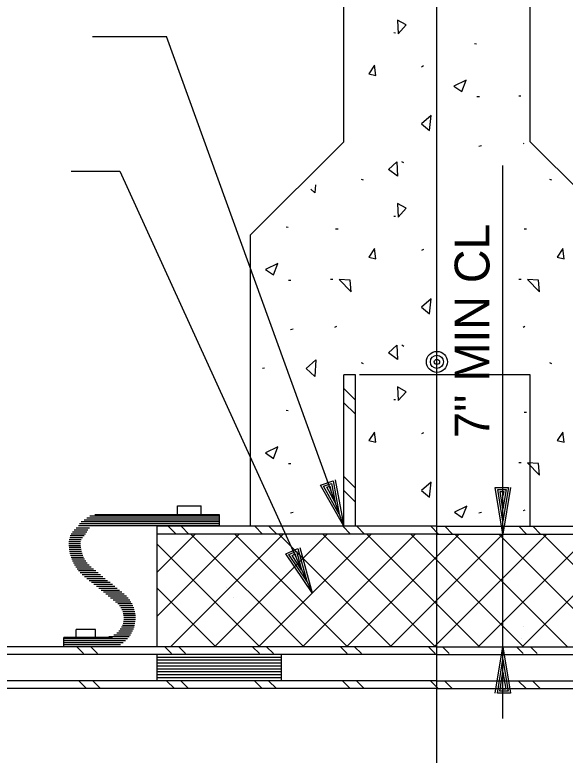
# Model space of a CAD drawing. Extents: x 22422.9 to 22498.9, y 22369.6 to 22415.
# Drawn here: x 22428.867 to 22431.818, y 22392.447 to 22396.418 of the extents above; entities that cross this region are included whole.
import ezdxf

# ---------------------------------------------------------------- set-up
doc = ezdxf.new("R2010")
doc.units = 0
for name, color, linetype in [('Level 1', 7, 'Continuous'), ('Level 2', 7, 'Continuous'), ('Level 4', 7, 'Continuous'), ('Level 44', 7, 'Continuous'), ('Level 7', 7, 'Continuous'), ('Level 8', 7, 'Continuous')]:
    doc.layers.add(name, color=color, linetype=linetype)

msp = doc.modelspace()

# ---------------------------------------------------------------- linework, layer by layer
at = {"layer": 'Level 1'}
for p, q in [((22431.1304, 22388.8739), (22431.1304, 22398.3655)), ((22431.4842, 22393.6331), (22431.4842, 22395.6099)), ((22430.6068, 22393.865), (22430.6068, 22393.865)), ((22430.6304, 22393.7998), (22430.6304, 22393.7998)), ((22429.7392, 22393.7364), (22429.7392, 22393.7841)), ((22429.7392, 22393.7841), (22429.8666, 22393.7841)), ((22429.8666, 22393.7364), (22429.8666, 22393.7841)), ((22429.6304, 22393.029), (22429.6304, 22393.6748)), ((22431.1304, 22393.6748), (22429.6304, 22393.6748)), ((22431.1304, 22393.6748), (22432.6304, 22393.6748)), ((22431.1304, 22393.6331), (22429.6304, 22393.6331)), ((22431.1304, 22393.6331), (22432.6304, 22393.6331)), ((22431.4842, 22393.029), (22431.4842, 22393.6331)), ((22429.9996, 22393.3479), (22429.9996, 22393.3479)), ((22430.0407, 22393.2921), (22430.0407, 22393.2921)), ((22429.1952, 22393.0786), (22429.1952, 22393.1216)), ((22429.2988, 22393.1216), (22429.1952, 22393.1216)), ((22429.2988, 22393.0786), (22429.2988, 22393.1216)), ((22431.5921, 22393.1392), (22431.5921, 22393.1392)), ((22431.5816, 22393.0706), (22431.5816, 22393.0706)), ((22431.1304, 22393.029), (22428.1304, 22393.029)), ((22431.1304, 22393.029), (22434.1304, 22393.029)), ((22431.4842, 22392.6437), (22431.4842, 22393.029)), ((22431.1304, 22392.9873), (22428.1304, 22392.9873)), ((22430.2971, 22392.9717), (22429.6304, 22392.9717)), ((22430.2971, 22392.9561), (22429.6304, 22392.9561)), ((22431.1304, 22392.9873), (22434.1304, 22392.9873)), ((22430.2971, 22392.9404), (22429.6304, 22392.9404)), ((22430.2971, 22392.9248), (22429.6304, 22392.9248)), ((22430.2971, 22392.9092), (22429.6304, 22392.9092)), ((22430.2971, 22392.8936), (22429.6304, 22392.8936)), ((22430.2971, 22392.8779), (22429.6304, 22392.8779)), ((22430.2971, 22392.8623), (22429.6304, 22392.8623))]:
    msp.add_line(p, q, dxfattribs=at)
at = {"layer": 'Level 2'}
for p, q in [((22429.2839, 22396.3022), (22429.6806, 22396.3022)), ((22430.6304, 22393.6748), (22429.6806, 22396.3022)), ((22430.6304, 22393.6748), (22430.6304, 22394.4873)), ((22430.6929, 22394.4873), (22430.6304, 22394.4873)), ((22430.6929, 22393.6748), (22430.6929, 22394.4873)), ((22431.6304, 22394.4873), (22430.7153, 22394.4873)), ((22431.6304, 22393.6748), (22431.6304, 22394.4873)), ((22429.9649, 22393.7364), (22429.2964, 22393.7364)), ((22429.9649, 22393.6748), (22429.9649, 22393.7364)), ((22429.3915, 22393.0786), (22429.1291, 22393.0786)), ((22429.1291, 22393.029), (22429.1291, 22393.0786)), ((22429.6304, 22392.8467), (22429.6304, 22392.9873)), ((22430.2971, 22392.8467), (22430.2971, 22392.9873)), ((22431.1304, 22392.8467), (22424.4637, 22392.8467)), ((22431.1304, 22392.8467), (22437.7746, 22392.8467)), ((22431.1304, 22392.805), (22424.493, 22392.805)), ((22431.1304, 22392.805), (22437.765, 22392.805))]:
    msp.add_line(p, q, dxfattribs=at)
for points in [[(22429.1692, 22395.5789), (22429.4297, 22395.5789), (22430.4612, 22393.3171)], [(22430.5845, 22393.9233), (22430.6304, 22393.6748), (22430.5068, 22393.8952), (22430.5732, 22393.9193), (22430.6068, 22393.74), (22430.5229, 22393.8897), (22430.5656, 22393.9051), (22430.5842, 22393.8027), (22430.5391, 22393.8842), (22430.5567, 22393.8906), (22430.5606, 22393.8679)], [(22431.5255, 22393.8825), (22431.4842, 22393.6331), (22431.4428, 22393.8825), (22431.5135, 22393.8825), (22431.4842, 22393.7025), (22431.4562, 22393.8718), (22431.5015, 22393.8718), (22431.4842, 22393.7691), (22431.4695, 22393.8611), (22431.4882, 22393.8611), (22431.4842, 22393.8385)], [(22429.9637, 22393.7082), (22429.2381, 22393.7082)], [(22429.9637, 22393.7187), (22429.2539, 22393.7187)], [(22429.9637, 22393.7291), (22429.2692, 22393.7291)], [(22429.9637, 22393.677), (22429.2078, 22393.677)], [(22429.9637, 22393.6874), (22429.2143, 22393.6874)], [(22429.9637, 22393.6978), (22429.2229, 22393.6978)], [(22429.2466, 22393.6331), (22429.1698, 22393.6331)], [(22429.253, 22393.6436), (22429.1762, 22393.6436)], [(22429.2588, 22393.654), (22429.1853, 22393.654)], [(22429.2678, 22393.6644), (22429.1956, 22393.6644)], [(22429.2195, 22393.5915), (22429.1569, 22393.5915)], [(22429.2226, 22393.6019), (22429.1576, 22393.6019)], [(22429.2298, 22393.6123), (22429.1614, 22393.6123)], [(22429.2395, 22393.6227), (22429.164, 22393.6227)], [(22429.2191, 22393.5811), (22429.1566, 22393.5811)], [(22429.2195, 22393.5706), (22429.1569, 22393.5706)], [(22429.2205, 22393.5602), (22429.1576, 22393.5602)], [(22429.2221, 22393.5498), (22429.1588, 22393.5498)], [(22430.3953, 22393.5611), (22430.4612, 22393.3171), (22430.3201, 22393.5268), (22430.3844, 22393.5561), (22430.4324, 22393.3802), (22430.3367, 22393.5226), (22430.3779, 22393.5414), (22430.4048, 22393.4408), (22430.3532, 22393.5184), (22430.3702, 22393.5262), (22430.376, 22393.5039)], [(22429.2245, 22393.5394), (22429.1605, 22393.5394)], [(22429.2275, 22393.529), (22429.1627, 22393.529)], [(22429.2313, 22393.5186), (22429.1653, 22393.5186)], [(22429.236, 22393.5081), (22429.1686, 22393.5081)], [(22429.2415, 22393.4977), (22429.1724, 22393.4977)], [(22429.2481, 22393.4873), (22429.1767, 22393.4873)], [(22429.2558, 22393.4769), (22429.1817, 22393.4769)], [(22429.2649, 22393.4665), (22429.1874, 22393.4665)], [(22429.2757, 22393.4561), (22429.1938, 22393.4561)], [(22429.2882, 22393.4456), (22429.201, 22393.4456)], [(22429.301, 22393.4352), (22429.2091, 22393.4352)], [(22429.3138, 22393.4248), (22429.2182, 22393.4248)], [(22429.3265, 22393.4144), (22429.2286, 22393.4144)], [(22429.3393, 22393.404), (22429.2405, 22393.404)], [(22429.3521, 22393.3936), (22429.2532, 22393.3936)], [(22429.3648, 22393.3831), (22429.266, 22393.3831)], [(22429.3776, 22393.3727), (22429.2788, 22393.3727)], [(22429.3904, 22393.3623), (22429.2915, 22393.3623)], [(22429.4031, 22393.3519), (22429.3043, 22393.3519)], [(22429.4159, 22393.3415), (22429.317, 22393.3415)], [(22429.4287, 22393.3311), (22429.3298, 22393.3311)], [(22429.4414, 22393.3206), (22429.3426, 22393.3206)], [(22429.4542, 22393.3102), (22429.3553, 22393.3102)], [(22429.4655, 22393.2998), (22429.3681, 22393.2998)], [(22429.475, 22393.2894), (22429.3809, 22393.2894)], [(22429.4831, 22393.279), (22429.3936, 22393.279)], [(22429.4899, 22393.2686), (22429.4064, 22393.2686)], [(22429.4957, 22393.2581), (22429.4188, 22393.2581)], [(22429.5006, 22393.2477), (22429.4284, 22393.2477)], [(22429.5046, 22393.2373), (22429.4358, 22393.2373)], [(22429.5078, 22393.2269), (22429.4414, 22393.2269)], [(22429.5104, 22393.2165), (22429.4457, 22393.2165)], [(22429.5122, 22393.2061), (22429.4487, 22393.2061)], [(22429.5134, 22393.1956), (22429.4506, 22393.1956)], [(22429.5114, 22393.154), (22429.4475, 22393.154)], [(22429.5129, 22393.1644), (22429.4498, 22393.1644)], [(22429.5137, 22393.1748), (22429.4511, 22393.1748)], [(22429.5139, 22393.1852), (22429.4514, 22393.1852)], [(22429.4984, 22393.1123), (22429.4243, 22393.1123)], [(22429.5028, 22393.1227), (22429.4326, 22393.1227)], [(22429.5064, 22393.1331), (22429.439, 22393.1331)], [(22429.5093, 22393.1436), (22429.4439, 22393.1436)], [(22429.4709, 22393.0706), (22429.1304, 22393.0706)], [(22429.4795, 22393.0811), (22429.3714, 22393.0811)], [(22429.4869, 22393.0915), (22429.3981, 22393.0915)], [(22429.4932, 22393.1019), (22429.4134, 22393.1019)], [(22429.4606, 22393.0602), (22429.1304, 22393.0602)], [(22429.4482, 22393.0498), (22429.1304, 22393.0498)], [(22429.4328, 22393.0394), (22429.1304, 22393.0394)], [(22429.4124, 22393.029), (22429.1304, 22393.029)], [(22431.4428, 22392.7796), (22431.4842, 22393.029), (22431.5255, 22392.7796), (22431.4548, 22392.7796), (22431.4842, 22392.9596), (22431.5122, 22392.7903), (22431.4668, 22392.7903), (22431.4842, 22392.893), (22431.4988, 22392.801), (22431.4802, 22392.801), (22431.4842, 22392.8236)]]:
    msp.add_lwpolyline(points, dxfattribs=at)
for radius in [0.0563, 0.0352, 0.0141]:
    msp.add_circle((22431.1303, 22394.5565), radius, dxfattribs=at)
at = {"layer": 'Level 44'}
for p, q in [((22430.9086, 22396.3196), (22430.8986, 22396.3203)), ((22431.3418, 22396.2611), (22431.3318, 22396.2628)), ((22431.0588, 22396.1433), (22431.0468, 22396.1373)), ((22431.3578, 22395.9773), (22431.3443, 22395.9773)), ((22431.5806, 22395.9821), (22431.5691, 22395.9821)), ((22431.3686, 22395.7156), (22431.3551, 22395.7118)), ((22431.5957, 22395.7268), (22431.5918, 22395.7253)), ((22430.9536, 22395.6231), (22430.9423, 22395.6298)), ((22430.7358, 22395.5301), (22430.7251, 22395.5351)), ((22431.7458, 22395.5301), (22431.7351, 22395.5351)), ((22430.9086, 22395.3358), (22430.8986, 22395.3366)), ((22430.3318, 22395.2773), (22430.3218, 22395.2791)), ((22430.6008, 22395.2688), (22430.5873, 22395.2688)), ((22431.6108, 22395.2688), (22431.5973, 22395.2688)), ((22431.0588, 22395.1596), (22431.0468, 22395.1536)), ((22430.3478, 22394.9936), (22430.3343, 22394.9936)), ((22430.5718, 22394.9983), (22430.5591, 22394.9983)), ((22431.5818, 22394.9983), (22431.5691, 22394.9983)), ((22430.5916, 22394.7453), (22430.5818, 22394.7416)), ((22431.6016, 22394.7453), (22431.5918, 22394.7416)), ((22430.3586, 22394.7318), (22430.3451, 22394.7281)), ((22430.9536, 22394.6393), (22430.9423, 22394.6461)), ((22430.7358, 22394.5463), (22430.7251, 22394.5513)), ((22431.7458, 22394.5463), (22431.7351, 22394.5513)), ((22430.2056, 22394.5223), (22430.1946, 22394.5213)), ((22430.9086, 22394.3521), (22430.8986, 22394.3528)), ((22430.3318, 22394.2936), (22430.3218, 22394.2953)), ((22431.6108, 22394.2851), (22431.5973, 22394.2851)), ((22431.0588, 22394.1758), (22431.0468, 22394.1698)), ((22430.3478, 22394.0098), (22430.3343, 22394.0098)), ((22431.5818, 22394.0146), (22431.5691, 22394.0146)), ((22430.3586, 22393.7481), (22430.3451, 22393.7443)), ((22431.3686, 22393.7481), (22431.3551, 22393.7443)), ((22431.6016, 22393.7616), (22431.5918, 22393.7578))]:
    msp.add_line(p, q, dxfattribs=at)
for points in [[(22430.9231, 22396.3161), (22430.9658, 22396.3641), (22430.9181, 22396.3896)], [(22430.8028, 22396.0926), (22430.7958, 22396.1473), (22430.7651, 22396.1016)], [(22431.2633, 22396.0066), (22431.2871, 22396.0678), (22431.2208, 22396.0356)], [(22431.0993, 22395.8783), (22431.0481, 22395.8336), (22431.0906, 22395.7978)], [(22430.9181, 22395.5523), (22430.8701, 22395.5886), (22430.9161, 22395.6293)], [(22430.9231, 22395.3323), (22430.9658, 22395.3803), (22430.9181, 22395.4058)], [(22430.8028, 22395.1088), (22430.7958, 22395.1636), (22430.7651, 22395.1178)], [(22431.8128, 22395.1088), (22431.8058, 22395.1636), (22431.7751, 22395.1178)], [(22430.2533, 22395.0228), (22430.2771, 22395.0841), (22430.2108, 22395.0518)], [(22430.6656, 22394.9951), (22430.6056, 22394.9983), (22430.6706, 22394.9318)], [(22431.6756, 22394.9951), (22431.6156, 22394.9983), (22431.6806, 22394.9318)], [(22431.0993, 22394.8946), (22431.0481, 22394.8498), (22431.0906, 22394.8141)], [(22430.9181, 22394.5686), (22430.8701, 22394.6048), (22430.9161, 22394.6456)], [(22430.4758, 22394.4783), (22430.4296, 22394.5211), (22430.4808, 22394.5668)], [(22430.9231, 22394.3486), (22430.9658, 22394.3966), (22430.9181, 22394.4221)], [(22430.8028, 22394.1251), (22430.7958, 22394.1798), (22430.7651, 22394.1341)], [(22431.8128, 22394.1251), (22431.8058, 22394.1798), (22431.7751, 22394.1341)], [(22430.2533, 22394.0391), (22430.2771, 22394.1003), (22430.2108, 22394.0681)], [(22431.6756, 22394.0113), (22431.6156, 22394.0146), (22431.6806, 22393.9481)], [(22431.0993, 22393.9108), (22431.0481, 22393.8661), (22431.0906, 22393.8303)], [(22431.2663, 22393.721), (22431.29, 22393.7822), (22431.2238, 22393.75)]]:
    msp.add_lwpolyline(points, close=True, dxfattribs=at)
msp.add_lwpolyline([(22430.4783, 22395.5059), (22430.4758, 22395.4621), (22430.4539, 22395.4823)], dxfattribs=at)
at = {"layer": 'Level 7'}
for p, q in [((22430.6304, 22395.7373), (22430.6304, 22397.6134)), ((22431.6304, 22395.7373), (22431.6304, 22397.6134)), ((22430.1304, 22395.2373), (22430.6304, 22395.7373)), ((22432.1304, 22395.2373), (22431.6304, 22395.7373)), ((22430.1304, 22393.6748), (22430.1304, 22395.2373))]:
    msp.add_line(p, q, dxfattribs=at)
at = {"layer": 'Level 8'}
for p, q in [((22431.4842, 22393.7025), (22431.4842, 22393.7025)), ((22431.4842, 22393.6331), (22431.4842, 22393.6331)), ((22430.4324, 22393.3802), (22430.4324, 22393.3802)), ((22430.4612, 22393.3171), (22430.4612, 22393.3171)), ((22431.4842, 22393.029), (22431.4842, 22393.029)), ((22431.4842, 22392.9596), (22431.4842, 22392.9596))]:
    msp.add_line(p, q, dxfattribs=at)
for points in [[(22430.6929, 22394.3506), (22430.6304, 22394.4131)], [(22430.6929, 22394.2752), (22430.6304, 22394.3377)], [(22430.6929, 22393.8792), (22430.6304, 22393.9417)], [(22430.6929, 22393.8038), (22430.6304, 22393.8663)], [(22429.7314, 22393.6331), (22429.6898, 22393.6748)], [(22429.7999, 22393.6331), (22429.7582, 22393.6748)], [(22430.1959, 22393.6331), (22430.1542, 22393.6748)], [(22430.2713, 22393.6331), (22430.2297, 22393.6748)], [(22430.6673, 22393.6331), (22430.6256, 22393.6748)], [(22430.7427, 22393.6331), (22430.7011, 22393.6748)], [(22431.1387, 22393.6331), (22431.097, 22393.6748)], [(22431.2141, 22393.6331), (22431.1725, 22393.6748)], [(22431.6101, 22393.6331), (22431.5685, 22393.6748)], [(22431.6855, 22393.6331), (22431.6439, 22393.6748)], [(22429.6304, 22393.1934), (22430.0701, 22393.6331)], [(22429.6304, 22393.4291), (22429.8344, 22393.6331)], [(22429.7017, 22393.029), (22430.3058, 22393.6331)], [(22430.4158, 22393.029), (22429.8116, 22393.6331)], [(22429.9374, 22393.029), (22430.5415, 22393.6331)], [(22430.6515, 22393.029), (22430.0473, 22393.6331)], [(22430.1731, 22393.029), (22430.7773, 22393.6331)], [(22430.8872, 22393.029), (22430.283, 22393.6331)], [(22430.4088, 22393.029), (22431.013, 22393.6331)], [(22431.1229, 22393.029), (22430.5187, 22393.6331)], [(22430.6445, 22393.029), (22431.2487, 22393.6331)], [(22431.3586, 22393.029), (22430.7544, 22393.6331)], [(22430.8802, 22393.029), (22431.4844, 22393.6331)], [(22431.5943, 22393.029), (22430.9901, 22393.6331)], [(22431.1159, 22393.029), (22431.7201, 22393.6331)], [(22431.83, 22393.029), (22431.2258, 22393.6331)], [(22431.3516, 22393.029), (22431.9558, 22393.6331)], [(22432.0657, 22393.029), (22431.4615, 22393.6331)], [(22431.5873, 22393.029), (22432.1915, 22393.6331)], [(22432.3014, 22393.029), (22431.6972, 22393.6331)], [(22430.1801, 22393.029), (22429.6304, 22393.5786)], [(22429.9444, 22393.029), (22429.6304, 22393.3429)], [(22429.2355, 22392.9925), (22429.1991, 22393.029)], [(22429.311, 22392.9925), (22429.2745, 22393.029)], [(22429.7069, 22392.9925), (22429.6705, 22393.029)], [(22429.7824, 22392.9925), (22429.7459, 22393.029)], [(22430.1783, 22392.9925), (22430.1419, 22393.029)], [(22430.2538, 22392.9925), (22430.2173, 22393.029)], [(22430.6498, 22392.9925), (22430.6133, 22393.029)], [(22430.7252, 22392.9925), (22430.6887, 22393.029)], [(22431.1212, 22392.9925), (22431.0847, 22393.029)], [(22431.1966, 22392.9925), (22431.1601, 22393.029)], [(22431.5926, 22392.9925), (22431.5561, 22393.029)], [(22431.668, 22392.9925), (22431.6315, 22393.029)], [(22429.2512, 22392.805), (22429.2095, 22392.8467)], [(22429.3266, 22392.805), (22429.2849, 22392.8467)], [(22429.7226, 22392.805), (22429.6809, 22392.8467)], [(22429.798, 22392.805), (22429.7563, 22392.8467)], [(22430.194, 22392.805), (22430.1523, 22392.8467)], [(22430.2694, 22392.805), (22430.2277, 22392.8467)], [(22430.6654, 22392.805), (22430.6237, 22392.8467)], [(22430.7408, 22392.805), (22430.6991, 22392.8467)], [(22431.1368, 22392.805), (22431.0951, 22392.8467)], [(22431.2122, 22392.805), (22431.1705, 22392.8467)], [(22431.6082, 22392.805), (22431.5665, 22392.8467)], [(22431.6836, 22392.805), (22431.6419, 22392.8467)]]:
    msp.add_lwpolyline(points, dxfattribs=at)

# ---------------------------------------------------------------- texts
at = {"layer": 'Level 4'}
msp.add_text("7'' MIN CL ", height=0.186667, rotation=90, dxfattribs=at).set_placement((22431.4119, 22394.1481))

doc.saveas('drawing.dxf')
